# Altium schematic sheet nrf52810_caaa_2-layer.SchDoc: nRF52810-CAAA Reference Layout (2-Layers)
size A4; Revision: 1.0; SheetNumber: 1; SheetTotal: 1; DrawnBy: RUBR; DocumentSize: A4; PCAName: nRF52810-CAAA Reference Layout (2-Layers)
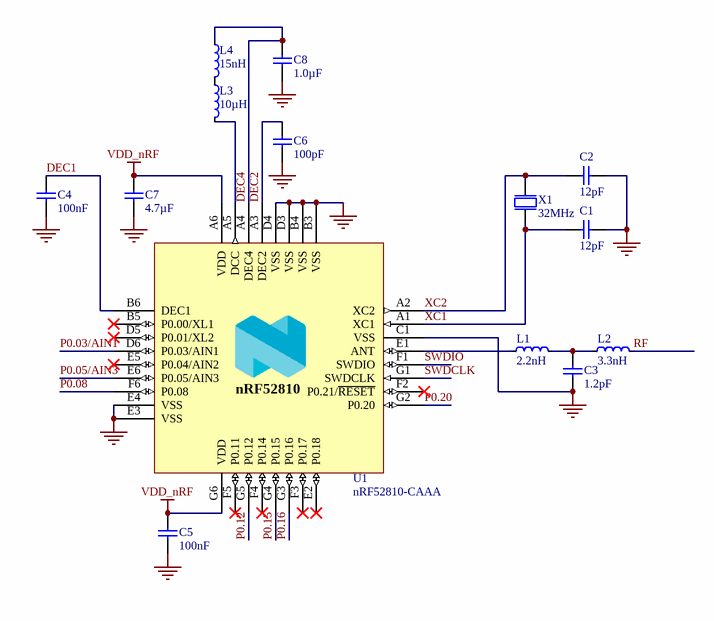
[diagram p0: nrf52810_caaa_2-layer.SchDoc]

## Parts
C1  12pF  [CAPC0603X03L_C]
C2  12pF  [CAPC0603X03L_C]
C3  1.2pF  [CAPC0603X03L_C]
C4  100nF  [CAPC0603X03L_C]
C5  100nF  [CAPC0603X03L_C]
C6  100pF  [CAPC0603X03L_C]
C7  4.7µF  [CAPC1608X06L]
C8  1.0µF  [CAPC1005X04L]
L1  2.2nH  [INDC0603X03L_C]
L2  3.3nH  [INDC0603X03L_C]
L3  10µH  [INDC1608X06L]
L4  15nH  [INDC1005X04L]
U1  nRF52810-CAAA  [BGA33C40P6X6_247X246X50]
X1  32MHz  [BT-XTAL_2016]

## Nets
GND: C1.1 C2.1 C3.1 C4.2 C5.2 C6.1 C7.2 C8.1 U1.B3(VSS) U1.B4(VSS) U1.C1(VSS) U1.D3(VSS) U1.D4(VSS) U1.E3(VSS) U1.E4(VSS) X1.2(GND) X1.4(GND)
VDD_nRF: C5.1 C7.1 U1.A6(VDD) U1.G6(VDD)
DEC1: C4.1 U1.B6(DEC1)
DEC2: C6.2 U1.A3(DEC2)
DEC4: C8.2 L4.1 U1.A4(DEC4)
P0.03/AIN1: U1.D6(P0.03/AIN1)
P0.05/AIN3: U1.E6(P0.05/AIN3)
P0.08: U1.F6(P0.08)
P0.12: U1.G5(P0.12)
P0.15: U1.G4(P0.15)
P0.16: U1.G3(P0.16)
P0.20: U1.G2(P0.20)
RF: L2.2
SWDCLK: U1.G1(SWDCLK)
SWDIO: U1.F1(SWDIO)
XC1: C1.2 U1.A1(XC1) X1.1(inp)
XC2: C2.2 U1.A2(XC2) X1.3(out)
NetC3_2: C3.2 L1.2 L2.1
NetL1_1: L1.1 U1.E1(ANT)
NetL3_1: L3.1 L4.2
NetL3_2: L3.2 U1.A5(DCC)

Not connected (* = marked no-connect by the designer): U1 B5(P0.00/XL1)* D5(P0.01/XL2)* E2(P0.18)* E5(P0.04/AIN2)* F2(P0.21/~{RESET})* F3(P0.17)* F4(P0.14)* F5(P0.11)*

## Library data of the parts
C1 C2 = C0201-12p: Capacitor, NP0, ±2%
C3 = C0201-1.2p: Capacitor, NP0, ±5%
C4 C5 = C0201-100n: Capacitor, X5R, ±10%
C6 = C0201-100p: Capacitor, NP0, ±2%
C7 = C0603-4µ7: Capacitor, X5R, ±10%
C8 = C0402-1µ0: Capacitor, X5R, ±5%
L1 = L0201-2n2: High frequency chip inductor ±5%
L2 = L0201-3n3: High frequency chip inductor ±5%
L3 = L0603-10µ: Chip inductor, IDC,min = 50 mA, ±20%
L4 = L0402-15n: High frequency chip inductor ±10%
U1 = nRF52810-CAAA: Multi-protocol Bluetooth Low Energy, ANT and 2.4GHz proprietary system-on-chip; Manufacturer: Nordic Semiconductor
X1 = XTAL_SMD2016_32MHz_8pF_General: XTAL SMD 2016, 32MHz, Cl=8pF, Total Tol: ±40ppm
